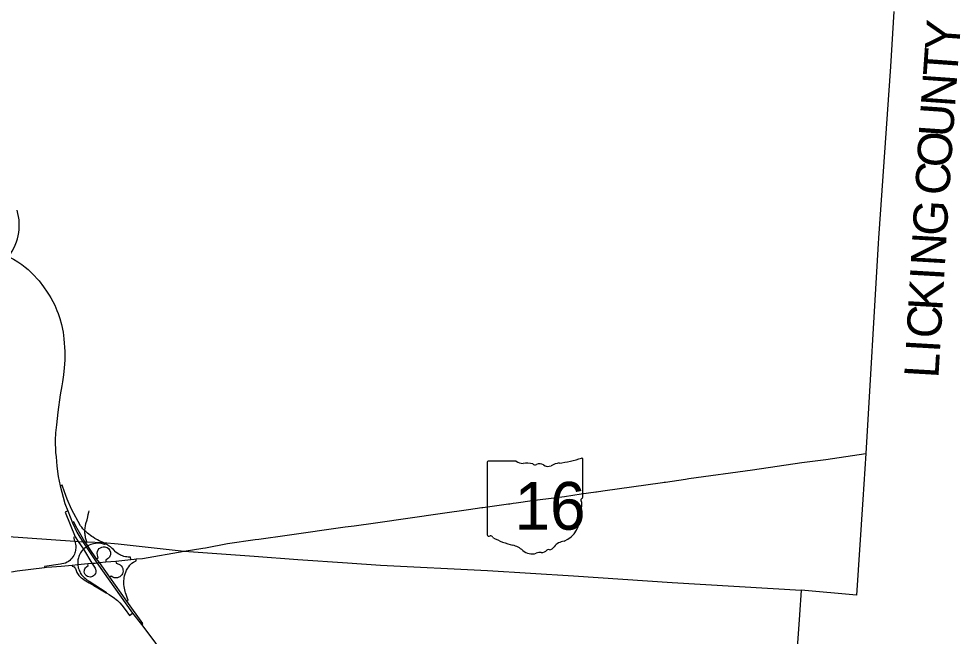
# Model space of a CAD drawing. Extents: x -1146 to -445, y -1283 to -822.
# Drawn here: x -786.6 to -718, y -1048.9 to -1003.9 of the extents above; entities that cross this region are included whole.
import ezdxf

# ---------------------------------------------------------------- set-up
doc = ezdxf.new("R2010")
doc.units = 0
for name, color, linetype in [('GM_X_Adjacent_County_Text', 7, 'Continuous'), ('GM_X_County', 7, 'Continuous'), ('GM_X_Interchange_Ramps', 7, 'Continuous'), ('GM_X_Interstate_Route', 7, 'Continuous'), ('GM_X_Interstate_Shield', 7, 'Continuous'), ('GM_X_State_Route', 7, 'Continuous'), ('GM_X_State_Shield', 7, 'Continuous'), ('GM_X_Township', 7, 'Continuous')]:
    doc.layers.add(name, color=color, linetype=linetype)

msp = doc.modelspace()

# ---------------------------------------------------------------- linework, layer by layer
at = {"layer": 'GM_X_County'}
msp.add_lwpolyline([(-722.786, -1003.387), (-723.025, -1007.4), (-723.916, -1019.919), (-723.932, -1020.299), (-724.826, -1035.597), (-725.049, -1038.96), (-725.51, -1045.915), (-729.553, -1045.554), (-729.679, -1047.366), (-730.581, -1060.332), (-730.732, -1062.497), (-730.857, -1064.3), (-731.27, -1070.236), (-731.413, -1072.292), (-731.874, -1078.923), (-738.201, -1078.491), (-751.672, -1077.572), (-752.243, -1086.092), (-752.566, -1090.897), (-753.436, -1103.447)], dxfattribs=at)
at = {"layer": 'GM_X_Interchange_Ramps'}
for points in [[(-778.425, -1043.328), (-778.438, -1043.157), (-778.605, -1043.147), (-778.705, -1043.14), (-778.815, -1043.124), (-778.931, -1043.097), (-779.019, -1043.071), (-779.106, -1043.038), (-779.185, -1043.003), (-779.257, -1042.966), (-779.343, -1042.915), (-779.435, -1042.851), (-779.503, -1042.797), (-779.695, -1042.605), (-779.772, -1042.53), (-779.835, -1042.474), (-779.914, -1042.409), (-779.997, -1042.347), (-780.062, -1042.303), (-780.122, -1042.266), (-780.214, -1042.207), (-780.445, -1042.096), (-780.717, -1041.967), (-780.841, -1041.906), (-780.949, -1041.848), (-781.055, -1041.787), (-781.178, -1041.71), (-781.264, -1041.652), (-781.363, -1041.581), (-781.479, -1041.491), (-781.591, -1041.398), (-781.709, -1041.291), (-781.766, -1041.234), (-781.819, -1041.182), (-781.914, -1041.082), (-782.003, -1040.98), (-782.097, -1040.863), (-782.746, -1039.654), (-783.057, -1038.928), (-783.26, -1038.387), (-783.429, -1037.916), (-783.569, -1037.969)], [(-783.022, -1039.778), (-783.218, -1039.882), (-782.483, -1041.668), (-782.261, -1042.02), (-781.872, -1042.577), (-781.26, -1043.605), (-781.029, -1043.971), (-780.996, -1044.042), (-780.972, -1044.158), (-780.976, -1044.247), (-781.005, -1044.347), (-781.061, -1044.443), (-781.133, -1044.515), (-781.209, -1044.562), (-781.289, -1044.591), (-781.368, -1044.604), (-781.473, -1044.597), (-781.581, -1044.56), (-781.661, -1044.507), (-781.744, -1044.415), (-781.793, -1044.313), (-781.812, -1044.221), (-781.81, -1044.133), (-781.798, -1044.07), (-781.771, -1043.999), (-781.73, -1043.932), (-781.657, -1043.856), (-781.531, -1043.767), (-781.55, -1043.631)], [(-781.712, -1042.112), (-781.632, -1042.043), (-781.658, -1041.968), (-781.682, -1041.891), (-781.701, -1041.822), (-781.719, -1041.748), (-781.736, -1041.659), (-781.749, -1041.575), (-781.759, -1041.49), (-781.765, -1041.41), (-781.767, -1041.334), (-781.768, -1041.269), (-781.766, -1041.234), (-781.763, -1041.154), (-781.757, -1041.077), (-781.75, -1041.021), (-781.735, -1040.879), (-781.697, -1040.705), (-781.615, -1040.434), (-781.562, -1040.229), (-781.523, -1040.048), (-781.491, -1039.88), (-781.468, -1039.786)], [(-777.65, -1048.076), (-777.534, -1047.997), (-778.709, -1046.364), (-779.959, -1044.624), (-780.716, -1043.556), (-780.917, -1043.272), (-781.444, -1042.527), (-781.565, -1042.339), (-781.712, -1042.112), (-781.766, -1042.03), (-781.977, -1041.71), (-782.421, -1040.91), (-782.569, -1040.585), (-782.68, -1040.652)], [(-782.483, -1041.668), (-782.598, -1041.729), (-782.581, -1041.78), (-782.544, -1041.882), (-782.508, -1042.001), (-782.481, -1042.107), (-782.459, -1042.218), (-782.442, -1042.33), (-782.435, -1042.405), (-782.435, -1042.496), (-782.443, -1042.598), (-782.455, -1042.674), (-782.474, -1042.761), (-782.5, -1042.847), (-782.534, -1042.936), (-782.576, -1043.024), (-782.637, -1043.129), (-782.714, -1043.234), (-782.785, -1043.313), (-782.877, -1043.398), (-782.971, -1043.469), (-783.068, -1043.53), (-783.193, -1043.584), (-783.301, -1043.618), (-783.445, -1043.654), (-783.551, -1043.673), (-784.721, -1043.829), (-784.71, -1043.915)], [(-780.214, -1042.207), (-780.337, -1042.223), (-780.481, -1042.181), (-780.617, -1042.158), (-780.745, -1042.145), (-780.869, -1042.149), (-780.988, -1042.158), (-781.154, -1042.19), (-781.233, -1042.207), (-781.346, -1042.241), (-781.459, -1042.286), (-781.565, -1042.339), (-781.673, -1042.406), (-781.757, -1042.474), (-781.872, -1042.577), (-781.979, -1042.67), (-782.043, -1042.759), (-782.09, -1042.832), (-782.146, -1042.935), (-782.187, -1043.029), (-782.217, -1043.11), (-782.244, -1043.198), (-782.263, -1043.28), (-782.277, -1043.357), (-782.287, -1043.436), (-782.292, -1043.523), (-782.293, -1043.604), (-782.289, -1043.688), (-782.288, -1043.699), (-782.28, -1043.77), (-782.267, -1043.852), (-782.249, -1043.933), (-782.217, -1044.042), (-782.184, -1044.129), (-782.147, -1044.213), (-782.107, -1044.288), (-782.064, -1044.361), (-782.014, -1044.434), (-781.959, -1044.504), (-781.894, -1044.578), (-781.833, -1044.638), (-781.736, -1044.722), (-781.618, -1044.811), (-781.461, -1044.916), (-780.207, -1045.713), (-780.228, -1045.75)], [(-780.917, -1043.272), (-780.811, -1043.195), (-780.859, -1043.008), (-780.866, -1042.866), (-780.853, -1042.743), (-780.804, -1042.633), (-780.725, -1042.535), (-780.635, -1042.466), (-780.545, -1042.425), (-780.437, -1042.401), (-780.325, -1042.403), (-780.232, -1042.425), (-780.144, -1042.465), (-780.059, -1042.527), (-779.991, -1042.605), (-779.952, -1042.671), (-779.909, -1042.805), (-779.902, -1042.886), (-779.914, -1042.991), (-779.941, -1043.075), (-779.981, -1043.151), (-780.044, -1043.228), (-780.118, -1043.289), (-780.245, -1043.376), (-780.236, -1043.509)], [(-782.699, -1043.736), (-782.687, -1043.821), (-782.558, -1043.868), (-782.495, -1043.925), (-782.46, -1043.982), (-782.442, -1044.05), (-782.415, -1044.132), (-782.38, -1044.214), (-782.348, -1044.28), (-782.311, -1044.344), (-782.257, -1044.424), (-782.211, -1044.482), (-782.164, -1044.536), (-782.114, -1044.587), (-782.063, -1044.632), (-782.011, -1044.675), (-781.951, -1044.717), (-781.896, -1044.752), (-781.702, -1044.881), (-781.46, -1045.023), (-781.113, -1045.225), (-780.704, -1045.472), (-780.228, -1045.75), (-780.176, -1045.781), (-780.003, -1045.887), (-779.84, -1045.989), (-779.712, -1046.072), (-779.607, -1046.147), (-779.497, -1046.237), (-779.404, -1046.317), (-779.327, -1046.392), (-779.234, -1046.481), (-779.083, -1046.644), (-778.837, -1046.966), (-778.512, -1047.4), (-778.29, -1047.247)], [(-779.51, -1043.438), (-779.488, -1043.603), (-779.299, -1043.662), (-779.191, -1043.727), (-779.115, -1043.799), (-779.049, -1043.894), (-779.012, -1043.98), (-778.992, -1044.07), (-778.988, -1044.17), (-779.003, -1044.272), (-779.036, -1044.364), (-779.082, -1044.444), (-779.146, -1044.519), (-779.226, -1044.583), (-779.301, -1044.624), (-779.401, -1044.656), (-779.519, -1044.668), (-779.642, -1044.652), (-779.731, -1044.621), (-779.848, -1044.544), (-779.959, -1044.624)], [(-778.709, -1046.364), (-778.607, -1046.286), (-778.662, -1046.165), (-778.72, -1046.019), (-778.767, -1045.885), (-778.805, -1045.761), (-778.836, -1045.648), (-778.862, -1045.534), (-778.887, -1045.407), (-778.903, -1045.305), (-778.922, -1045.142), (-778.928, -1045.026), (-778.926, -1044.893), (-778.913, -1044.748), (-778.899, -1044.648), (-778.873, -1044.524), (-778.833, -1044.381), (-778.789, -1044.255), (-778.727, -1044.114), (-778.644, -1043.96), (-778.576, -1043.854), (-778.499, -1043.751), (-778.429, -1043.666), (-778.341, -1043.588), (-778.237, -1043.522), (-778.021, -1043.413), (-778.038, -1043.288)]]:
    msp.add_lwpolyline(points, dxfattribs=at)
at = {"layer": 'GM_X_Interstate_Route'}
for points in [[(-791.34, -1019.627), (-791.204, -1019.679), (-790.791, -1019.839), (-789.175, -1020.491), (-788.32, -1020.835), (-787.49, -1021.194), (-786.976, -1021.447), (-786.651, -1021.637), (-786.378, -1021.818), (-786.128, -1022.019), (-785.909, -1022.199), (-785.61, -1022.472), (-785.107, -1023.027), (-784.779, -1023.449), (-784.514, -1023.836), (-784.367, -1024.072), (-784.257, -1024.247), (-783.97, -1024.791), (-783.806, -1025.17), (-783.729, -1025.389)], [(-783.729, -1025.389), (-783.601, -1025.755), (-783.478, -1026.197), (-783.365, -1026.771), (-783.303, -1027.254), (-783.23, -1028.175), (-783.231, -1028.793), (-783.279, -1029.356), (-783.337, -1029.876)], [(-783.337, -1029.876), (-783.394, -1030.39), (-783.447, -1030.67)], [(-783.447, -1030.67), (-783.574, -1031.333), (-783.738, -1032.579), (-783.849, -1033.523), (-783.902, -1034.097), (-783.931, -1034.642), (-783.902, -1035.54), (-783.874, -1035.852)], [(-783.874, -1035.852), (-783.812, -1036.524), (-783.709, -1037.271), (-783.569, -1037.969)], [(-783.569, -1037.969), (-783.23, -1039.247), (-783.022, -1039.778)], [(-783.022, -1039.778), (-782.68, -1040.652), (-782.353, -1041.339), (-782.144, -1041.692), (-781.92, -1042.032), (-781.673, -1042.406), (-780.901, -1043.574)], [(-780.901, -1043.574), (-778.29, -1047.247)], [(-778.29, -1047.247), (-777.65, -1048.076)], [(-777.65, -1048.076), (-776.881, -1049.072), (-776.292, -1049.891), (-775.908, -1050.57), (-775.838, -1050.706)]]:
    msp.add_lwpolyline(points, dxfattribs=at)
at = {"layer": 'GM_X_Interstate_Shield'}
msp.add_ellipse((-792.414, -1018.941), major_axis=(5.859, 0), ratio=0.8, start_param=4.913747, end_param=6.513751, dxfattribs=at)
at = {"layer": 'GM_X_State_Route'}
for points in [[(-737.864, -1037.454), (-737.733, -1037.435), (-733.084, -1036.785), (-729.504, -1036.267), (-727.745, -1036.028), (-724.826, -1035.597)], [(-743.998, -1038.324), (-739.668, -1037.722), (-739.538, -1037.702), (-739.428, -1037.686)], [(-739.428, -1037.686), (-737.97, -1037.47), (-737.864, -1037.454)], [(-747.392, -1038.802), (-746.799, -1038.725), (-745.586, -1038.549), (-744.52, -1038.397)], [(-744.52, -1038.397), (-744.469, -1038.389), (-743.998, -1038.324)], [(-750.788, -1039.26), (-750.54, -1039.225), (-750.321, -1039.195), (-749.158, -1039.032), (-747.392, -1038.802)], [(-769.091, -1041.841), (-767.027, -1041.554), (-762.793, -1040.958), (-762.135, -1040.863), (-760.588, -1040.643), (-755.707, -1039.948), (-753.79, -1039.685), (-752.83, -1039.545), (-752.747, -1039.533)], [(-752.747, -1039.533), (-750.877, -1039.272), (-750.788, -1039.26)], [(-772.972, -1042.472), (-771.373, -1042.165), (-769.348, -1041.877), (-769.091, -1041.841)], [(-778.167, -1043.302), (-778.038, -1043.288), (-777.565, -1043.251), (-774.525, -1042.732), (-773.173, -1042.51), (-772.972, -1042.472)], [(-787.129, -1044.223), (-786.719, -1044.164), (-784.71, -1043.915), (-784.571, -1043.898), (-784.172, -1043.864), (-783.501, -1043.806)], [(-783.501, -1043.806), (-782.699, -1043.736), (-782.288, -1043.699), (-781.55, -1043.631), (-781.26, -1043.605), (-781.031, -1043.585)], [(-781.031, -1043.585), (-780.901, -1043.574), (-780.716, -1043.556), (-780.236, -1043.509), (-779.51, -1043.438), (-778.425, -1043.328), (-778.167, -1043.302)]]:
    msp.add_lwpolyline(points, dxfattribs=at)
at = {"layer": 'GM_X_State_Shield'}
for p, q in [((-752.43, -1036.244), (-752.43, -1041.528)), ((-750.323, -1036.153), (-752.361, -1036.153)), ((-745.469, -1038.786), (-745.469, -1036.023)), ((-745.47, -1038.786), (-745.469, -1038.786))]:
    msp.add_line(p, q, dxfattribs=at)
for centre, radius, start, end in [((-752.35, -1036.233), 0.0806, 98.1301, 188.1301), ((-749.837, -1035.54), 0.782, 231.61951, 271.11188), ((-749.578, -1039.12), 2.808, 80.48669, 94.98827), ((-748.94, -1036.206), 0.226, 219.79206, 297.10237), ((-748.609, -1036.816), 0.469, 54.46668, 119.14113), ((-747.007, -1037.767), 1.485, 97.34618, 120.76885), ((-747.948, -1028.951), 7.382, 275.84447, 288.90645), ((-745.546, -1036.011), 0.0775, 351.86209, 97.738), ((-748.004, -1035.979), 0.564, 233.85621, 294.82819), ((-745.487, -1038.989), 0.12, 107.94398, 210.33697), ((-746.25, -1039.338), 0.72, 340.03296, 23.64957), ((-745.552, -1038.797), 0.0829, 289.60381, 7.73413), ((-745.191, -1039.943), 0.524, 136.8065, 186.92959), ((-747.535, -1040.294), 1.846, 292.30889, 8.98584), ((-752.349, -1041.539), 0.0814, 171.95839, 258.30661), ((-752.337, -1040.999), 0.621, 267.33899, 280.60386), ((-752.21, -1041.832), 0.224, 29.74838, 93.27175), ((-749.384, -1037.086), 5.331, 240.41292, 257.1985), ((-750.973, -1043.901), 1.668, 47.18416, 75.83597), ((-748.038, -1042.04), 0.597, 282.87319, 323.27711), ((-746.756, -1043.011), 1.011, 94.40312, 142.57675), ((-749.169, -1041.859), 1.058, 230.70037, 286.29184), ((-748.557, -1043.685), 0.87, 85.69512, 111.20995), ((-748.48, -1042.254), 0.564, 268.77702, 315.54927), ((-747.97, -1042.766), 0.159, 65.75173, 132.64842)]:
    msp.add_arc(centre, radius, start, end, dxfattribs=at)
at = {"layer": 'GM_X_Township'}
for points in [[(-792.543, -1041.281), (-782.508, -1042.001), (-782.261, -1042.02), (-781.92, -1042.032), (-781.766, -1042.03), (-781.632, -1042.043), (-780.445, -1042.096), (-779.332, -1042.189), (-774.525, -1042.732), (-769.42, -1043.093), (-766.24, -1043.317), (-762.626, -1043.572), (-760.208, -1043.742), (-752.407, -1044.118), (-746.15, -1044.528), (-738.94, -1044.999), (-729.553, -1045.554)], [(-725.51, -1045.915), (-729.553, -1045.554)]]:
    msp.add_lwpolyline(points, dxfattribs=at)

# ---------------------------------------------------------------- texts
at = {"layer": 'GM_X_Adjacent_County_Text'}
for s, rotation, p in [('Y', 85.91445, (-718.043, -1006.326)), ('T', 85.91575, (-718.176, -1008.191)), ('N', 85.94064, (-718.333, -1010.396)), ('U', 86.03546, (-718.486, -1012.601)), ('O', 86.22404, (-718.631, -1014.805)), ('C', 86.3185, (-718.762, -1016.834)), ('G', 86.55199, (-718.942, -1019.796)), ('N', 86.65652, (-719.071, -1022.002)), ('I', 86.68915, (-719.13, -1023.023)), ('K', 86.6903, (-719.258, -1025.231)), ('C', 86.69298, (-719.375, -1027.262)), ('I', 86.69149, (-719.434, -1028.283)), ('L', 86.69264, (-719.542, -1030.15))]:
    msp.add_text(s, height=2.5, rotation=rotation, dxfattribs=at).set_placement(p)
at = {"layer": 'GM_X_State_Shield'}
msp.add_text('16', height=3.4805, dxfattribs=at).set_placement((-750.445, -1041.155))

doc.saveas('drawing.dxf')
